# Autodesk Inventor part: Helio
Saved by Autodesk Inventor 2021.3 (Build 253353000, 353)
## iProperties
Created: 2022-08
Part Number: Helio
Material: Generic
Document SubType Name: Modeling
Designer: Administrator
Density: 1 g/cm^3
Appearance: Default
Title: Helio v5
Author: Administrator
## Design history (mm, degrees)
feature "Helio" [Body]
feature "Socket Body" [Body]
feature "Shade Ring" [Body]
feature "Shade Ring +Collar" [Body]
feature "Socket" [Body]
feature "Body1"
feature "Metal Strain Relief" [Body]
feature "Fabric Cord (1)" [Body]
feature "Stem (Threaded)" [Body]
feature "Cap (Threaded)" [Body]
feature "T9-Bulb" [Body]
body "Solid1"
body "Solid2"
body "Solid3"
body "Solid4"
body "Solid5"
body "Solid6"
body "Solid7"
body "Solid8"
body "Solid9"
body "Solid10"
body "Solid11"
